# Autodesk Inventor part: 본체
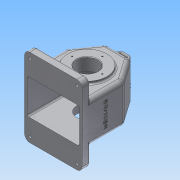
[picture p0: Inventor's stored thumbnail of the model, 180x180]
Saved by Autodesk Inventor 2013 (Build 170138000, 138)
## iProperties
Created: 2016-12
Part Number: 본체
Material: 알루미늄 6061
Document SubType Name: Modeling
Designer: Administrator
Density: 2.71 g/cm^3
Mass: 1062.36 g
Surface Area: 1145.91 cm^2
Volume: 392.016 cm^3
Author: Administrator
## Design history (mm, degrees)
sketch "스케치1"
  geometry: L1 (23.491, 60)-(-23.491, 60); L2 (-23.491, 60)-(-55, 15); L3 (-55, 15)-(-55, -65); L4 (-55, -65)-(55, -65); L5 (55, -65)-(55, 15); L6 (55, 15)-(23.491, 60); 2 further points
  constraints: 12 end point, 2 parallel, 1 horizontal, 1 midpoint, 1 perpendicular, 1 vertical alignment
  dimensions: "d0" = 125 distance between parallel lines of L4 L1; "d3" = 35 deg angle of L3 L2; "d4" = 35 deg angle of L6 L5; "d5" = 110 distance of L3.end L4.end; "d6" = 80 distance from line of L4 L5.end; "d7" = 80 distance of L3.end L2.end; "d8" = 65 distance from line of L4 point (0, 0)
extrude "돌출1" new body sketch "스케치1" stored distance "d9" = 77; taper "d10" = 0 deg
feature "쉘1" dims "d26" = 5
sketch "스케치2"
  geometry: C1 r 37.5 at (0, 0); 1 further point
  constraints: 1 centre point, 1 coincident
  dimensions: "d11" = 75 diameter of C1
extrude "돌출2" join sketch "스케치2" distance "d12" = 5; taper "d13" = 0 deg
sketch "스케치3"
  geometry: C1 r 31 at (0, 0); 1 further point
  constraints: 1 centre point, 1 coincident
  dimensions: "d14" = 62 diameter of C1
extrude "돌출3" join sketch "스케치3" distance "d15" = 10; taper "d16" = 0 deg
hole "구멍1" diameter "d19" = 40; stored, may be unused: countersink angle "d23" = 90 deg, drill point angle "d25" = 0 deg; dims "d17" = 10, "d18" = 10, "d20" = 6, "d21" = 4, "d22" = 2, "d24" = 15
node "작업 평면1"
sketch "스케치5"
  geometry: C1 r 27 at (0, 0); 1 further point
  constraints: 1 centre point, 1 coincident
  dimensions: "d29" = 54 diameter of C1
extrude "돌출4" join sketch "스케치5" distance "d30" = 24; taper "d31" = 0 deg
feature "면 기울기1" dims angle "d32" = -45 deg
hole "구멍2" diameter "d35" = 40; stored, may be unused: countersink angle "d39" = 90 deg, drill point angle "d41" = 0 deg; dims "d33" = 10, "d34" = 10, "d36" = 6, "d37" = 4, "d38" = 2, "d40" = 24
chamfer "모따기1" distance "d42" = 1; stored, may be unused: second distance "d43" = 2, angle "d44" = 45 deg
sketch "스케치6"
  geometry: C1 r 31 at (0, 0) reference; 1 further point
  constraints: 1 vertical alignment
  dimensions: "d45" = 26 distance of C1.centre point (0, 26)
hole "구멍3" sketch "스케치6" at (0, 26) diameter "d46" = 2.459; stored, may be unused: countersink angle "d50" = 90 deg, drill point angle "d52" = 118 deg; dims "d47" = 6, "d48" = 4, "d49" = 2, "d51" = 8
fillet "모깎기1" dims "d56" = 3
fillet "모깎기2" dims "d57" = 3
sketch "스케치7"
  geometry: C1 r 37.5 at (0, 0) reference; 1 further point
  constraints: 1 vertical alignment
  dimensions: "d58" = 29 distance of C1.centre point (0, 29)
hole "구멍4" sketch "스케치7" at (0, 29) diameter "d59" = 2.459; stored, may be unused: countersink angle "d63" = 90 deg, drill point angle "d65" = 118 deg; dims "d60" = 6, "d61" = 4, "d62" = 2, "d64" = 8
sketch "스케치8"
  geometry: L1 (110, -77)-(110, 0) reference; L2 (0, 0)-(110, 0) reference; L3 (0, -77)-(0, 0) reference; L4 (110, -77)-(0, -77) reference; L5 (0, 36.5)-(110, 36.5); L6 (110, 36.5)-(110, -113.5); L7 (110, -113.5)-(0, -113.5); L8 (0, -113.5)-(0, 36.5); L9 (0, 36.5)-(110, -113.5); L10 (110, 36.5)-(0, -113.5); 1 further point
  constraints: 12 end point, 2 midpoint, 2 parallel, 1 horizontal, 1 perpendicular
  dimensions: "d69" = 110 distance of L6.end L7.end; "d70" = 150 distance of L5.end L6.end
extrude "돌출5" join sketch "스케치8" distance "d71" = 15; taper "d72" = 0 deg
fillet "모깎기3" dims "d73" = 10
sketch "스케치9"
  geometry: 2 further points
  dimensions: "d74" = 45 horizontal distance of point (55, 38.5) point (10, 103.5); "d76" = 65 vertical distance of point (10, 103.5) point (55, 38.5)
hole "구멍5" sketch "스케치9" at (10, 103.5) diameter "d77" = 5; stored, may be unused: countersink angle "d81" = 90 deg, drill point angle "d83" = 118 deg; dims "d78" = 5, "d79" = 12, "d80" = 5, "d82" = 8
fillet "모깎기5" dims "d91" = 8
fillet "모깎기6" dims "d92" = 10
fillet "모깎기7" dims "d93" = 3
node "작업 평면3"
sketch "스케치10"
  geometry: L1 (95.5, -18)-(-34.5, -18) reference; 1 further point
  constraints: 1 other
  dimensions: "d113" = 45 distance from line of L1 point (30.5, 27)
feature "엠보싱1" sketch "스케치10" dims "d0" = 125, "d3" = 35 deg, "d4" = 35 deg, "d5" = 110, "d6" = 80, "d7" = 80, "d8" = 65, "d18" = 10, "d95" = 0.5, "d96" = 0
node "작업 평면2"
sketch "스케치12"
  geometry: L1 (-18.285, 60)-(18.285, 60) reference; L2 (-12.5, 60)-(-12.5, 75); L3 (-12.5, 75)-(12.5, 75); L4 (12.5, 75)-(12.5, 60); L5 (50, -65)-(-50, -65) reference; L6 (7.5, 60)-(7.5, 70); L7 (7.5, 70)-(-7.5, 70); L8 (-7.5, 70)-(-7.5, 60); L9 (-7.5, 60)-(-12.5, 60); L10 (7.5, 60)-(12.5, 60); 2 further points
  constraints: 16 end point, 4 perpendicular, 2 collinear, 2 point on line, 1 midpoint, 1 vertical alignment, 2 other
  dimensions: "d102" = 25 distance of L2.end L3.end; "d104" = 140 distance between parallel lines of L5 L3; "d105" = 15 distance of L6.end L7.end
extrude "돌출6" join sketch "스케치12" distance "d106" = 8; taper "d107" = 0 deg
fillet "모깎기10" dims "d110" = 8
fillet "모깎기11" dims "d111" = 1
fillet "모깎기12" dims "d112" = 1
fillet "모깎기13" dims "d114" = 3
fillet "모깎기14" dims "d115" = 3
fillet "모깎기15" dims "d116" = 3
node "솔리드1"
pattern_circular "원형 패턴1" dims angle "d54" = 360 deg
pattern_circular "원형 패턴2" dims angle "d67" = 360 deg
pattern_linear "직사각형 패턴1" dims "d86" = 90
mirror "대칭1"
other parameters: "d28" = -24, "d101" = 26
